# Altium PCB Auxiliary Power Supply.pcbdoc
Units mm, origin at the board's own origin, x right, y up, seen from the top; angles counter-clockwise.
Board outline 48 x 29.97 mm, 2 copper layers (Top Layer, Bottom Layer), stack 1.575 mm thick; 26 components, 15 nets, 76 pads, 29 vias.
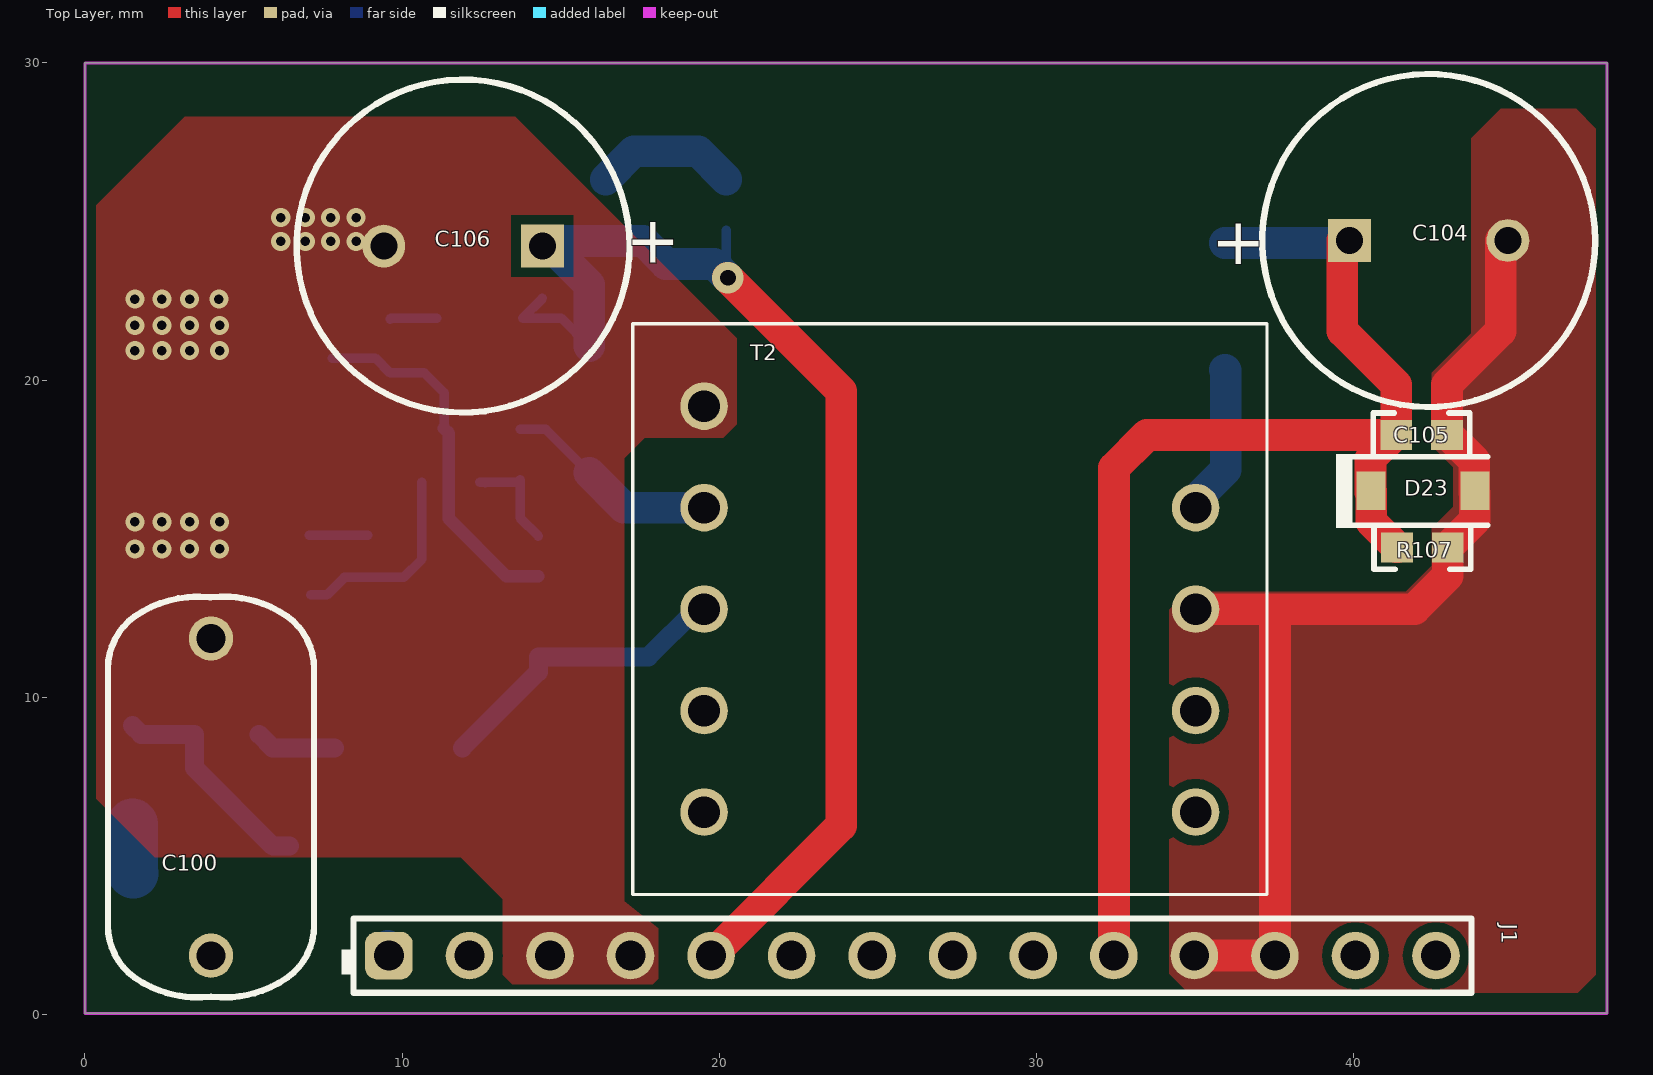
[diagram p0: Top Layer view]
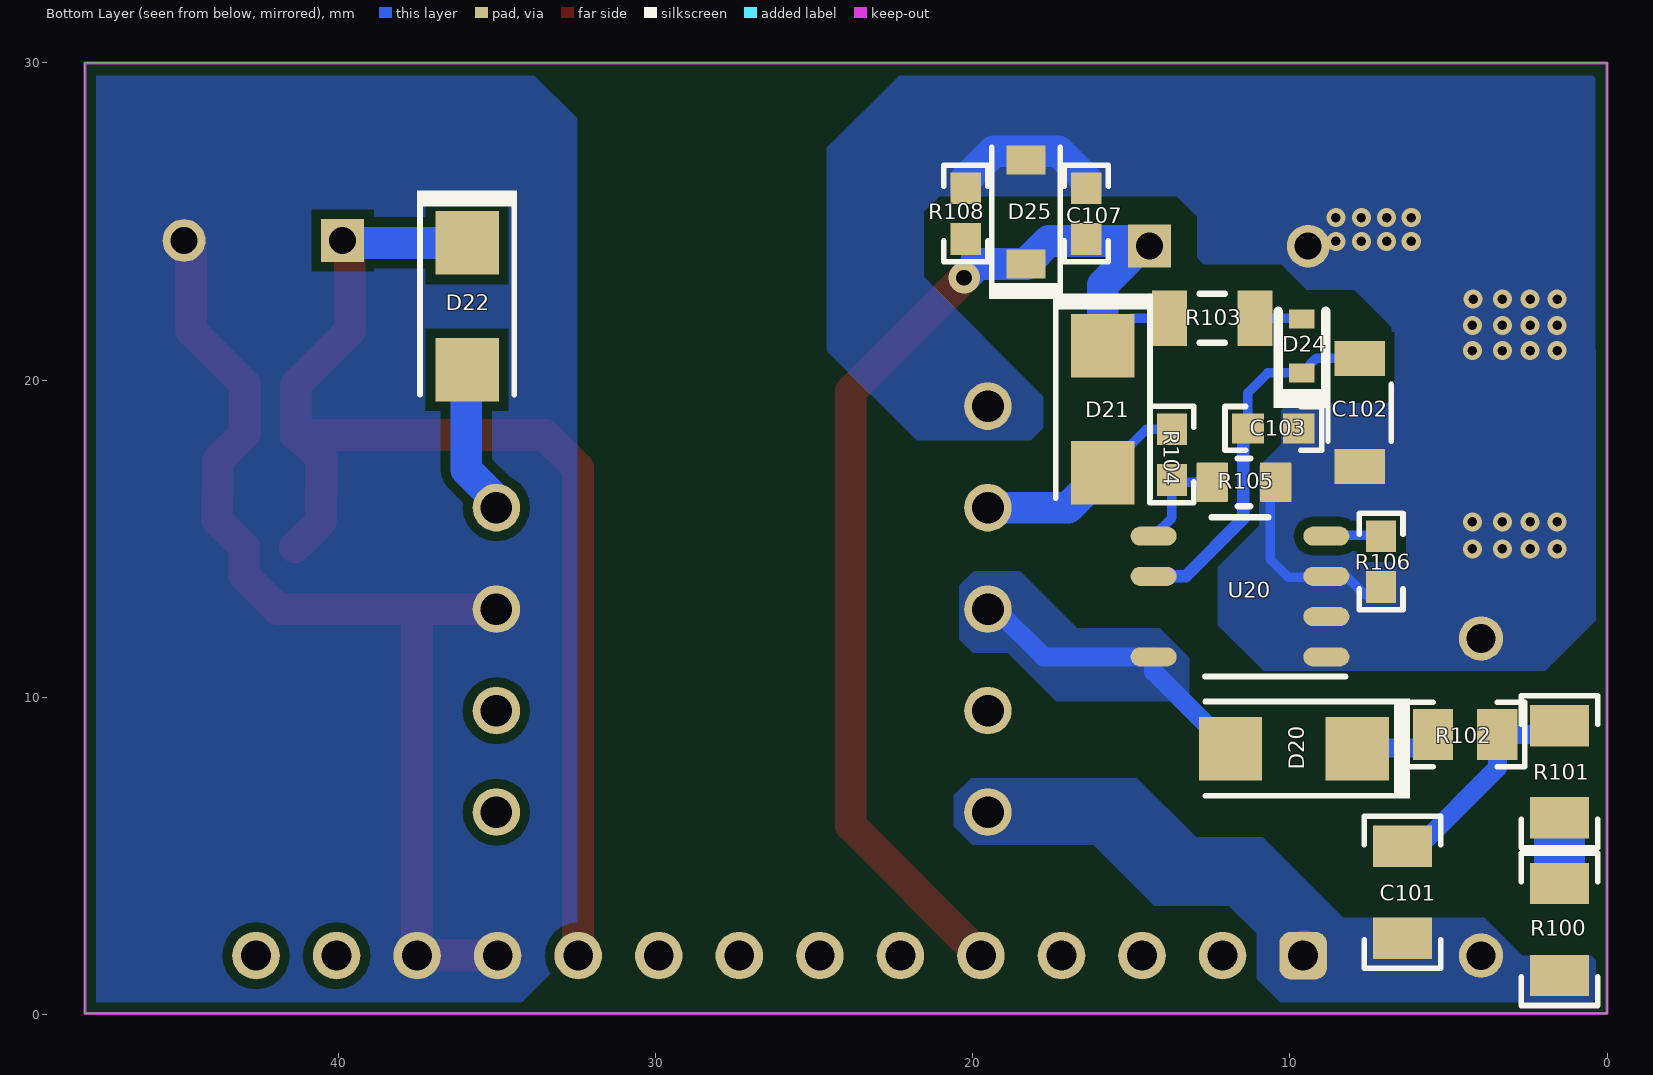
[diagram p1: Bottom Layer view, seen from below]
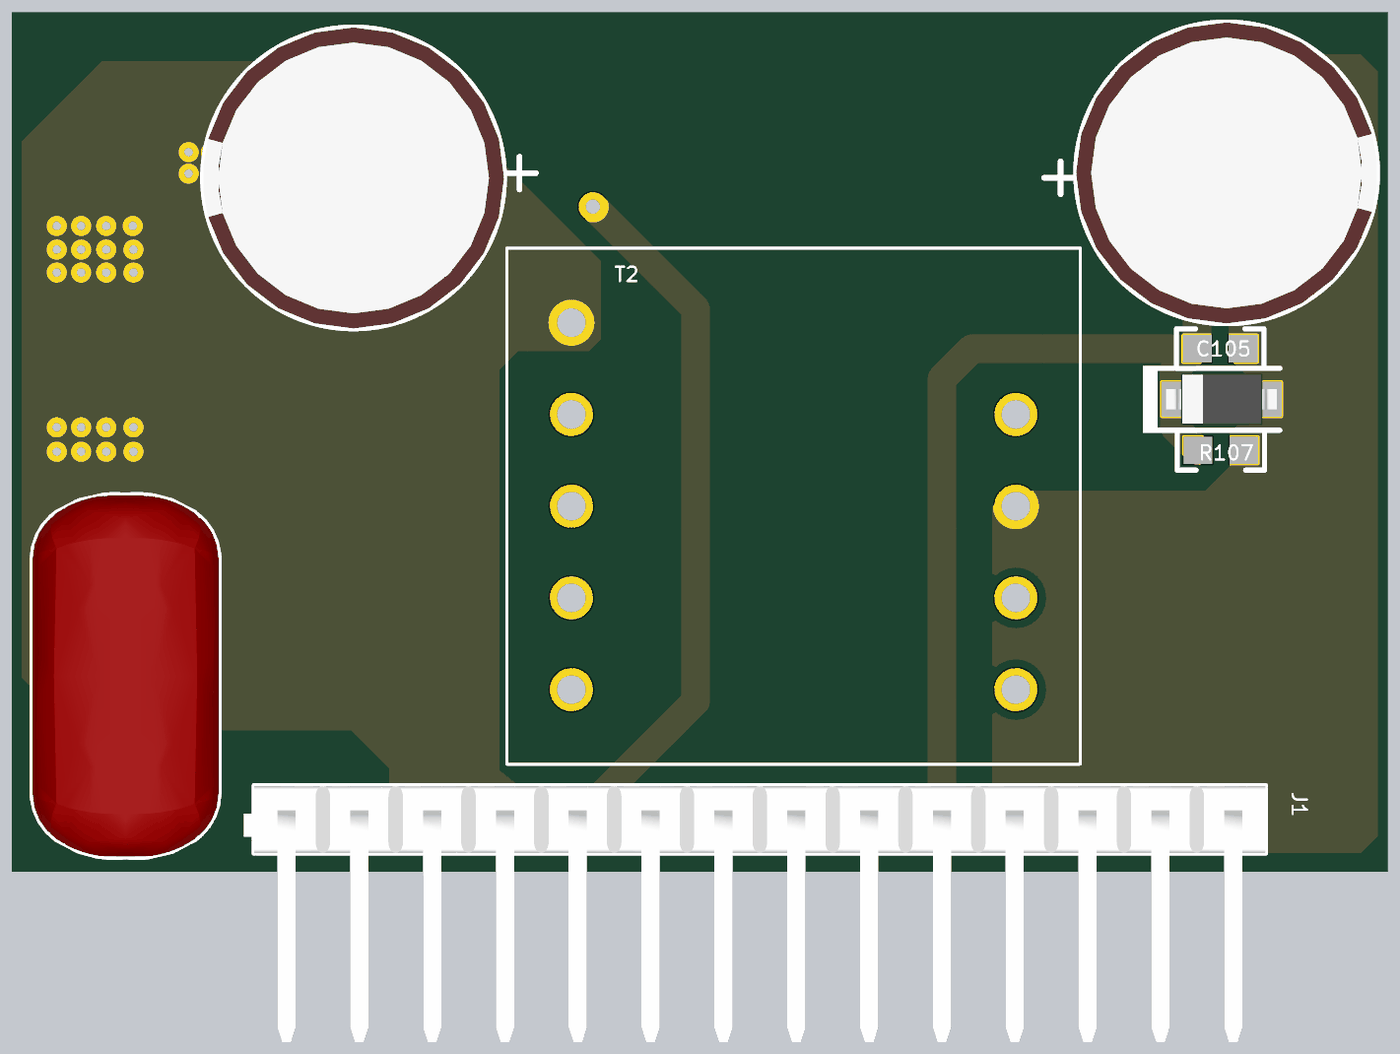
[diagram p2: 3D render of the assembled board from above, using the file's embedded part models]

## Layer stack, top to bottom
Top Solder: solder mask 0.0102, Solder Resist, Dk 3.5
Top Layer: signal copper 0.0356
Dielectric1: core 1.5037, FR-4, Dk 4.8
Bottom Layer: signal copper 0.0356
Bottom Solder: solder mask 0.0102, Solder Resist, Dk 3.5

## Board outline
0,0.025 48,0.025 48,30 0,30

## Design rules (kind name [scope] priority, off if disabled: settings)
AcuteAngle [All] p1: minimum=4.50000000000000E+0001 checktracksonly=FALSE
AssemblyTestPointUsage [All] p1: valid=2
BoardOutlineClearance BoardOutlineClearance_MountingHoles [OnCopper and InComponentClass('Mounting Holes')] p1: gap=0.4 ignorepadtopadclearanceinfootprint=FALSE
BoardOutlineClearance BoardOutlineClearance_Poly [OnCopper and IsPoly] p2: gap=0.3 ignorepadtopadclearanceinfootprint=FALSE
BoardOutlineClearance [OnCopper and Not InComponentClass('Logo') and not InComponentClass('FiducialMark') and not InRegion(1000,500,4000,800) and not InPoly] p3: gap=0.3 ignorepadtopadclearanceinfootprint=FALSE
Clearance Clearance_Keepouts [((IsTrack Or IsArc) And Not InPoly) And IsFree and IsKeepOut vs ((IsTrack Or IsArc) And Not InPoly) And IsFree and IsKeepOut] p1: gap=0 ignorepadtopadclearanceinfootprint=FALSE
Clearance Clearance_Poly [InPolygon] p2: gap=0.3 ignorepadtopadclearanceinfootprint=FALSE except(0: Arc-Hole Track-Hole SMDPad-Hole THPad-Hole Via-Hole Fill-Hole Poly-Hole Region-Hole Text-Hole)
Clearance Clearance_FiducialMark [IsKeepOut and InComponentClass('FiducialMark') vs IsPad and InComponentClass('FiducialMark')] p3: gap=0 ignorepadtopadclearanceinfootprint=FALSE
Clearance [All] p4: gap=0.2 ignorepadtopadclearanceinfootprint=FALSE except(0: Arc-Hole Track-Hole SMDPad-Hole THPad-Hole Via-Hole Fill-Hole Poly-Hole Region-Hole Text-Hole)
ComponentClearance ComponentClearance_MountingHoles_FiducialMarks [InComponentClass('Mounting Holes') vs InComponentClass('FiducialMark')] p1: gap=1.27 collisioncheckmode=3 verticalgap=0.254 showdistances=FALSE
ComponentClearance ComponentClearance_Shunt [InComponentClass('Header') vs InComponentClass('Shunt')] p2: gap=0 collisioncheckmode=3 verticalgap=0 showdistances=FALSE
ComponentClearance ComponentClearance_Logo [InComponentClass('Logo')] p3: gap=1.27 collisioncheckmode=3 verticalgap=0.254 showdistances=FALSE
ComponentClearance ComponentClearance_ScrewToNut [(HasFootprint('NY PMS 440 0025 PH')) vs (HasFootprint('Keystone_1902C'))] p4: gap=0.127 collisioncheckmode=3 verticalgap=0.254 showdistances=FALSE
ComponentClearance ComponentClearance_MountingHoles [InComponentClass('Mounting Holes')] p5: gap=6.35 collisioncheckmode=3 verticalgap=2540 showdistances=FALSE
ComponentClearance ComponentClearance_SmallPassives [HasFootprint('0201*') or HasFootprint('0402*') or HasFootprint('0508') or HasFootprint('0603*') or HasFootprint('0612') or HasFootprint('0805*') or HasFootprint('0815*') or HasFootprint('0830*') or HasFootprint('1206*') or HasFootprint('1210*') or HasFootprint('1808*') or HasFootprint('1812*') or HasFootprint('1825*') or HasFootprint('2010*') or HasFootprint('2220*') or HasFootprint('2225*') or HasFootprint('2512*') or HasFootprint('2728*') or HasFootprint('3518*') vs HasFootprint('0201*') or HasFootprint('0402*') or HasFootprint('0508') or HasFootprint('0603*') or HasFootprint('0612') or HasFootprint('0805*') or HasFootprint('0815*') or HasFootprint('0830*') or HasFootprint('1206*') or HasFootprint('1210*') or HasFootprint('1808*') or HasFootprint('1812*') or HasFootprint('1825*') or HasFootprint('2010*') or HasFootprint('2220*') or HasFootprint('2225*') or HasFootprint('2512*') or HasFootprint('2728*') or HasFootprint('3518*')] p6: gap=0.38 collisioncheckmode=3 verticalgap=0.254 showdistances=FALSE
ComponentClearance ComponentClearance_THtoSMT [IsThruComponent vs IsSMTComponent] p7: gap=0 collisioncheckmode=3 verticalgap=0 showdistances=FALSE
ComponentClearance ComponentClearance_THtoTH [IsThruComponent vs IsThruComponent] p8: gap=0 collisioncheckmode=3 verticalgap=0 showdistances=FALSE
ComponentClearance [All] p9: gap=0 collisioncheckmode=3 verticalgap=0 showdistances=FALSE
DiffPairsRouting [All] p1: maxlimit=2.54 minlimit=0.254 mostfreqgap=0.254 toplayer_minwidth=0.381 toplayer_maxwidth=0.381 toplayer_prefwidth=0.381 bottomlayer_minwidth=0.381 bottomlayer_maxwidth=0.381 bottomlayer_prefwidth=0.381 maxuncoupledlength=25.4
FabricationTestPointUsage TestPointUsage [All] p1: valid=2 allowmultiple=FALSE
FabricationTestpoint Testpoint [All] p1: side=3 testpointundercomponent=TRUE minsize=1.016 maxsize=2.54 preferedsize=1.524 minholesize=0 maxholesize=1.016 preferedholesize=0.813 testpointgrid=0.025 allowsidetop=TRUE allowsidebottom=TRUE usegrid=TRUE gridtolerance=0
FanoutControl Fanout_LCC [IsLCC] p1: bgadir=Out bgaviamode=Centered fanoutstyle=Auto fanoutdirection=Alternating viagrid=0.025 // Fanout_LCC (Default Rule)
FanoutControl Fanout_BGA [IsBGA] p2: bgadir=Out bgaviamode=Centered fanoutstyle=Auto fanoutdirection=Alternating viagrid=0.025 // Fanout_BGA (Default Rule)
FanoutControl Fanout_Default [All] p4: bgadir=Out bgaviamode=Centered fanoutstyle=Auto fanoutdirection=Alternating viagrid=0.025 // Fanout_Default (Default Rule)
FanoutControl Fanout_Small [(CompPinCount < 5)] p5: bgadir=Out bgaviamode=Centered fanoutstyle=Auto fanoutdirection=OutThenIn viagrid=0.025 // Fanout_Small (Default Rule)
HoleSize [All] p1: absolutevalues=TRUE maxlimit=6.375 minlimit=0.2 maxpercent=80.000 minpercent=20.000
MinimumAnnularRing MinimumAnnularRing_ThermalPadVias [IsVia and InAnyComponent] p1: minimumring=0.15
MinimumAnnularRing [All] p2: minimumring=0.203
MinimumSolderMaskSliver MinimumSolderMaskSliver_Logo [InComponentClass('Logo') vs InComponentClass('Logo')] p1: minsoldermaskwidth=0.018
MinimumSolderMaskSliver [All] p2: minsoldermaskwidth=0.1
PlaneConnect [All] p1: planeconnectstyle=Relief reliefexpansion=0.254 reliefentries=4 reliefconductorwidth=0.254 reliefairgap=0.254
PolygonConnect [All] p1: connectstyle=Direct reliefconductorwidth=0.254 reliefentries=4 polygonreliefangle="90 Angle" airgapwidth=0.254
RoutingVias ThermalPadVias [IsVia and InAnyComponent] p1: holewidth=0.2 width=0.5 viastyle="Through Hole" minholewidth=0.2 minwidth=0.5 maxholewidth=0.33 maxwidth=0.6
RoutingVias [All] p2: holewidth=0.406 width=0.864 viastyle="Through Hole" minholewidth=0.2 minwidth=0.66 maxholewidth=1.016 maxwidth=1.651
SilkToBoardRegionClearance [Not ((IsComment or IsDesignator) And (Hide <> 'False')) and not InRegion(1000,500,4000,800)] p1:
SilkToSilkClearance SilkToSilkClearance_Pb-FreeLogo [(HasFootprint('Pb-Free_Overlay_Medium') OR HasFootprint('Pb-Free_Overlay_Small')) vs (HasFootprint('Pb-Free_Overlay_Medium') OR HasFootprint('Pb-Free_Overlay_Small'))] p1: silktosilkclearance=0
SilkToSilkClearance [All] p2: silktosilkclearance=0.102
SilkToSolderMaskClearance SilkToComponentPadClearance [(IsPad or IsFill or IsRegion) and InAnycomponent] p1: minsilkscreentomaskgap=0.127 clearancetoexposedcopper=TRUE
SilkToSolderMaskClearance "Silk to Solder Mask Opening" [All] p2: minsilkscreentomaskgap=0.102 clearancetoexposedcopper=FALSE
SolderMaskExpansion [All] p1: expansion=0.05
Width [All] p1: maxlimit=2.54 minlimit=0.152 preferedwidth=0.254 checkconnectedcopper=TRUE
15 further rules are at their usual default settings.

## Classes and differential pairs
component class Header: J1

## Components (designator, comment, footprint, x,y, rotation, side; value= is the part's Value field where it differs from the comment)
C100 "ECW-FD2W474Q1" ECWFD_1260x650x1270 3.975,6.85 r90 top value=0.47uF
C101 "GRM31BR72J222KW01L" 1206 6.45,3.85 r90 bottom value=2200pF
C102 "C3216X5R1E476M160AC" 1206_190 7.8,18.975 r270 bottom value=47uF
C103 "GRM188R71E104KA01D" 0603 10.525,18.475 r180 bottom value=0.1uF
C104 "ELXZ250ELL471MJ16S" Chemi-Con_1000x1600 42.375,24.4 r0 top value=470uF
C105 "C0603C104K3RACTU" 0603 42.151,18.268 r0 top value=0.1uF
C106 "ELXZ250ELL471MJ16S" Chemi-Con_1000x1600 11.925,24.225 r180 top value=470uF
C107 "C0603C104K3RACTU" 0603 16.425,25.25 r90 bottom value=0.1uF
D20 "US1M-13-F" SMA 9.875,8.375 r0 bottom value=1000V
D21 "ES2DA-13-F" SMA 15.9,19.075 r270 bottom value=200V
D22 "ES2DA-13-F" SMA 35.95,22.325 r270 bottom value=200V
D23 "MMSZ4705T1G" SOD-123 42.2,16.505 r0 top value=18V
D24 "CDBU0245" SOD-523F 9.625,21.075 r90 bottom value=50V
D25 "MMSZ4705T1G" SOD-123 18.325,25.3 r90 bottom value=18V
J1 "TSW-114-08-L-S-RA" TE_4-644694-4 26.095,-0.182 r0 top
R100 "CRCW120620K0JNEA" 1206 1.5,2.675 r270 bottom value=20k
R101 "CRCW120620K0JNEA" 1206 1.5,7.65 r90 bottom value=20k
R102 "CRCW08050000Z0EA" 0805_HV 4.475,8.825 r180 bottom value=0
R103 "CRCW120620R0FKEA" 1206L 12.45,21.95 r180 bottom value=20.0
R104 "CRCW060351K0JNEA" 0603 13.725,17.65 r90 bottom value=51k
R105 "CRCW080518K2FKEA" 0805_HV1 11.45,16.775 r0 bottom value=18.2k
R106 "CRCW06031K50JNEA" 0603 7.125,14.275 r90 bottom value=1.5k
R107 "CRCW060318K0JNEA" 0603 42.175,14.725 r180 top value=18k
R108 "CRCW060318K0JNEA" 0603 20.225,25.25 r270 bottom value=18k
T2 "750344399" FLY_T1 27.275,12.775 r0 top
U20 "UCC28911DR" D0007A_N 11.575,13.175 r0 bottom

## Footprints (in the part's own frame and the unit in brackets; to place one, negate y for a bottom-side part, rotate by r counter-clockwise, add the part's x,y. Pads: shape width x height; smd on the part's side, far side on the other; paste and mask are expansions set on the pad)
0603 [mm] "0603 from SM-752 data"
  rect 1x0.95 smd: 1(-0.8,0) 2(0.8,0)
  silkscreen extent -1.52,-0.69 1.52,0.69, body extent -0.87,-0.47 0.87,0.47, height 1
0805_HV [mil] "0805 with 30mil clearance between pads"
  rect 50x63 smd: 1(-40,0) 2(40,0)
  silkscreen extent -74,-40 74,40, body extent -43,-29 43,29, height 57
0805_HV1 [mm] "Custom footprint based on analyzing multiple manufacturer recommendations"
  rrect10% 1x1.25 smd: 1(-1,0) 2(1,0)
  silkscreen extent -0.2,-0.75 0.2,0.75, body extent -1.1,-0.72 1.1,0.73, height 1.45
1206 [mm] "1206 from SM-752 data"
  rect 1.3x1.85 smd: 1(-1.45,0) 2(1.45,0)
  silkscreen extent -2.4,-1.21 2.4,1.21, body extent -1.7,-0.9 1.7,0.9, height 1.35
1206_190 [mm] "1206_190"
  rect 1.1x1.6 smd: 1(-1.7,0) 2(1.7,0)
  silkscreen extent -0.9,-1 0.9,1, body extent -1.75,-0.95 1.75,0.95, height 1.9
1206L [mm] "1206 from SM-752 data"
  rect 1.1x1.75 smd: 1(-1.35,0) 2(1.35,0)
  silkscreen extent -0.4,-0.77 0.4,0.77, body extent -1.7,-0.9 1.7,0.9, height 1.35
Chemi-Con_1000x1600 [mm] "TH, 2-Leads, Dia 10mm, Pin Spacing 5mm"
  rect 1.35x1.35 hole 0.85: 1(-2.5,0)
  round 1.35 hole 0.85: 2(2.5,0)
  silkscreen extent -5.25,-5.25 5.25,5.25, body extent -5.25,-5.25 5.26,5.25, height 17.5
D0007A_N [mm] "SOIC, 7-Leads, Body 4.9x3.9mm, Pitch 1.27mm, IPC Medium Density"
  oval 1.45x0.6 smd: 1(-2.725,1.905) 2(-2.725,0.635) 3(-2.725,-0.635) 4(-2.725,-1.905) 5(2.725,-1.905) 6(2.725,-0.635) 8(2.725,1.905)
  silkscreen extent -3.32,-2.5 1.1,2.52, body extent -3.01,-2.45 3.01,2.45, height 1.75
ECWFD_1260x650x1270 [mm] "TH, 2-Leads, Body 12.6x6.5mm"
  round 1.4 hole 0.9: 1(-5,0) 2(5,0)
  silkscreen extent -6.32,-3.25 6.32,3.25, body extent -6.31,-3.25 6.31,3.25, height 12.71
FLY_T1 [mm]
  round 1.5 hole 1: 1(7.75,3.2) 2(7.75,0) 3(-7.75,0) 4(-7.75,-6.4) 5(-7.75,3.2) 6(-7.75,6.4) ""(-7.75,-3.2) ""(7.75,-6.4) ""(7.75,-3.2)
  silkscreen extent -10,-9 10,9
SMA [mm] "Molded Diode, 2-Leads, Body 4.3x2.6mm, IPC Medium Density, based on OnSemi component dimensions and land pattern"
  rect 2x2 smd: 1(-2,0) 2(2,0)
  silkscreen extent -3.66,-1.57 2.79,1.57, body extent -2.6,-1.3 2.6,1.3, height 2.42
SOD-123 [mm] "On Semi recommended land pattern"
  rect 0.915x1.22 smd: 1(-1.637,0) 2(1.637,0)
  silkscreen extent -2.74,-1.17 2.03,1.17, body extent -1.93,-0.9 1.93,0.9, height 1.35
SOD-523F [mm] "COMCHIP"
  rect 0.6x0.8 smd paste-0.05: 1(-0.85,0) 2(0.85,0)
  silkscreen extent -1.95,-0.9 1.1,0.9, body extent -0.9,-0.5 0.9,0.5, height 0.85
TE_4-644694-4 [mm] "Header, 100 mil, 14x1, R/A, TH"
  rrect50% 1.5x1.5 hole 0.94: 1(-16.51,2.032)
  round 1.5 hole 0.94: 2(-13.97,2.032) 3(-11.43,2.032) 4(-8.89,2.032) 5(-6.35,2.032) 6(-3.81,2.032) 7(-1.27,2.032) 8(1.27,2.032) 9(3.81,2.032) 10(6.35,2.032) 11(8.89,2.032) 12(11.43,2.032) 13(13.97,2.032) 14(16.51,2.032)
  silkscreen extent -18,0.86 17.63,3.2, body extent -17.63,-5.74 17.63,3.2, height 6.67

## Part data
C100: "CAP, Film, 0.47 µF, 450 V, +/- 10%, TH", Cap_Case=12.6x6.5x12.7mm, Manufacturer=Panasonic, Supplier Part Number 1=P16727-ND, Tolerance_%=10, Value1=Unknown, Value2=450V, ValueDisplayed=0.47µF
C101: "CAP, CERM, 2200 pF, 630 V,+/- 10%, X7R, 1206", Cap_Case=1206, Manufacturer=MuRata, Supplier Part Number 1=490-3508-1-ND, TempCo=X7R, Tolerance_%=10, Value2=630V, ValueDisplayed=2200pF
C102: "CAP, CERM, 47 µF, 25 V,+/- 20%, X5R, 1206", Cap_Case=1206, Manufacturer=TDK, Supplier Part Number 1=445-8047-1-ND, TempCo=X5R, Tolerance_%=20, Value2=25V, ValueDisplayed=47µF
C103: library part CMP-0007404-4, "CAP, CERM, 0.1 uF, 25 V, +/- 10%, X7R, 0603", Cap_Case=0603, Manufacturer=MuRata, Supplier Part Number 1=490-1524-1-ND, TempCo=X7R, Tolerance_%=10%, Value1=Unknown, Value2=25V, ValueDisplayed=0.1uF
C104: library part CMP-0010480-1, "CAP, AL, 470 uF, 25 V, +/- 20%, AEC-Q200 Grade 2, TH", Cap_Case=10x16mm, Manufacturer=Chemi-Con, Supplier Part Number 1=565-1958-ND, Tolerance_%=20%, Value1=Unknown, Value2=25V, ValueDisplayed=470uF
C105 C107: "CAP, CERM, 0.1 µF, 25 V,+/- 10%, X7R, 0603", Cap_Case=0603, Manufacturer=Kemet, Supplier Part Number 1=399-1281-1-ND, TempCo=X7R, Tolerance_%=10, Value2=25V, ValueDisplayed=0.1µF
C106: "CAP, AL, 470 µF, 25 V, +/- 20%, AEC-Q200 Grade 2, TH", Cap_Case=10x16mm, Manufacturer=Chemi-Con, Supplier Part Number 1=565-1958-ND, Tolerance_%=20, Value2=25V, ValueDisplayed=470µF
D20: "Diode, Ultrafast, 1000 V, 1 A, SMA", Manufacturer="Diodes Inc.", Supplier Part Number 1=US1M-FDICT-ND, Value1=1A, Value2=1.7V
D21 D22: "Diode, Superfast Rectifier, 200 V, 2 A, SMA", Manufacturer="Diodes Inc.", Supplier Part Number 1=ES2DA-FDICT-ND, Value1=2A, Value2=0.92V
D23 D25: "Diode, Zener, 18 V, 500 mW, SOD-123", Manufacturer="ON Semiconductor", Power_W=0.5, Supplier Part Number 1=MMSZ4705T1GOSCT-ND, Value1=0.5W
D24: "Diode, Schottky, 50 V, 0.2 A, SOD-523F", Manufacturer="Comchip Technology", Supplier Part Number 1=641-1284-1-ND, Value1=0.2A, Value2=0.55V
J1: library part 4-644694-4, "Header, 100 mil, 14x1, Gold, R/A, TH", Color=Natural, Manufacturer=Samtec, Supplier Part Number 1=SAM1043-14-ND
R100 R101: "RES, 20 k, 5%, 0.25 W, 1206", Manufacturer=Vishay-Dale, Power_W=0.25, Supplier Part Number 1=541-20KECT-ND, TempCo="200 ppm/C", Tolerance_%=5, Value1=5%, Value2=0.25W, Value_Code=20k0, ValueDisplayed=20k
R102: "RES, 0, 5%, 0.125 W, 0805", Manufacturer=Vishay-Dale, Power_W=0.125, Supplier Part Number 1=541-0.0ACT-ND, TempCo="200 ppm/C", Tolerance_%=5, Value1=5%, Value2=0.125W, Value_Code=0000, ValueDisplayed=0
R103: "RES, 20.0, 1%, 0.25 W, 1206", Manufacturer=Vishay-Dale, Power_W=0.25, Supplier Part Number 1=541-20.0FCT-ND, TempCo="100 ppm/C", Tolerance_%=1, Value1=1%, Value2=0.25W, Value_Code=20R0, ValueDisplayed=20.0
R104: "RES, 51 k, 5%, 0.1 W, 0603", Manufacturer=Vishay-Dale, Power_W=0.1, Supplier Part Number 1=541-51KGCT-ND, TempCo="200 ppm/C", Tolerance_%=5, Value1=5%, Value2=0.1W, Value_Code=51k0, ValueDisplayed=51k
R105: "RES, 18.2 k, 1%, 0.125 W, 0805", Manufacturer=Vishay-Dale, Power_W=0.125, Supplier Part Number 1=541-18.2KCCT-ND, TempCo="100 ppm/C", Tolerance_%=1, Value1=1%, Value2=0.125W, Value_Code=18k2, ValueDisplayed=18.2k
R106: "RES, 1.5 k, 5%, 0.1 W, 0603", Manufacturer=Vishay-Dale, Power_W=0.1, Supplier Part Number 1=541-1.5KGCT-ND, TempCo="200 ppm/C", Tolerance_%=5, Value1=5%, Value2=0.1W, Value_Code=1k50, ValueDisplayed=1.5k
R107 R108: library part CMP-0025727-4, "RES, 18 k, 5%, 0.1 W, AEC-Q200 Grade 0, 0603", Manufacturer=Vishay-Dale, Power_W=100mW, Supplier Part Number 1=541-18KGCT-ND, TempCo="200 ppm/C", Tolerance_%=5%, Value2=0.1W, Value_Code=18k0, ValueDisplayed=18k
T2: library part "Trans3 Ideal", "750344399 Wuth", Manufacturer=Wurth
U20: library part CMP-0074093-2, "700V Flyback Switcher with Constant-Voltage Constant-Current and Primary-side Regulation, D0007A (SOIC-7)", Alternate Manufacturer="Texas Instruments", Alternate PartNumber=UCC28911D

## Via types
v1: diameter 0.6, hole 0.3, Top Layer to Bottom Layer, 28 vias
v2: diameter 1, hole 0.5, Top Layer to Bottom Layer, 1 vias

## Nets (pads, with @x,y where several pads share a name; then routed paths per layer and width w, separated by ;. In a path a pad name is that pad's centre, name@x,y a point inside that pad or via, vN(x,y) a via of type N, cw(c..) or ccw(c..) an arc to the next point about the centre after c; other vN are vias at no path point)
390V: C100.1 C101.1 J1.1 R100.2 T2.4 | length 0.1
  Bottom Layer w1: J1.1@9.547,2.15 J1.1@9.59,2.107
NetC101_2: C101.2 R101.2 R102.2 | length 7.1
  Bottom Layer w0.6: R101.2 1.775,8.825 R102.2 3.459,7.766 5.925,5.3 C101.2
NetD20_1: D20.1 R102.1 | length 2.6
  Bottom Layer w0.6: R102.1 5.916,8.4 D20.1@7.875,8.4
NetD20_2: D20.2 T2.3 U20.8 | length 9.5
  Bottom Layer w0.6: D20.2@11.9,8.4 14.3,10.8 U20.8 17.77,11.27 T2.3@19.275,12.775
NetD21_2: D21.2 R104.2 T2.5 | length 6.6
  Bottom Layer w0.3: R104.2 14.525,18.45 D21.2
  Bottom Layer w1: D21.2 17,15.975 T2.5@19.275,15.975
NetD22_2: D22.2 T2.1 | length 4.9
  Bottom Layer w1: T2.1@34.775,15.975 35.975,17.175 35.975,20.3 D22.2
NetD24_2: D24.2 R103.2 | length 1.5
  Bottom Layer w0.3: D24.2 9.65,21.95 R103.2
NetR100_1: R100.1 R101.1 | length 1.8
  Bottom Layer w0.3: R100.1@1.525,4.175 R100.1@1.525,4.45
  Bottom Layer w1.6: R101.1@1.5,6 1.5,4.475 R100.1@1.525,4.45
NetR104_1: R104.1 R105.2 U20.5 | length 3.3
  Bottom Layer w0.3: R105.2 R105.2@12.625,16.775 ; R105.2@12.625,16.755 R105.2@12.625,16.775 ; U20.5 13.725,15.655 R104.1 13.65,16.775 R105.2@12.625,16.775
NetR106_2: R106.2 U20.4 | length 1.8
  Bottom Layer w0.3: R106.2@7.075,15.1 U20.4@8.911,15.1
PGND: C100.2 C102.2 C103.2 C106.2 C107.2 D25.2 J1.3 J1.4 R105.1 R106.1 R108.1 T2.6 U20.1 U20.2 U20.3 | length 10.9
  Bottom Layer w0.3: R106.1@7.125,13.225 7.631,13.225 8.181,13.775 10.05,13.775 10.625,14.35 R105.1@10.625,16.775
  Bottom Layer w1: C107.2@16.425,26.325 17.313,27.213 19.338,27.213 R108.1@20.225,26.325
  other v1: 1.575,14.675 2.425,14.675 3.3,14.675 4.25,14.675 1.575,15.525 2.425,15.525 3.3,15.525 4.25,15.525 1.575,20.925 2.425,20.925 3.3,20.925 4.25,20.925 1.575,21.725 2.425,21.725 3.3,21.725 4.25,21.725 1.575,22.55 2.425,22.55 3.3,22.55 4.225,22.55 6.175,24.375 6.95,24.375 7.75,24.375 8.55,24.375 6.175,25.125 6.95,25.125 7.75,25.125 8.55,25.125
Pri_15V: C106.1 C107.1 D21.1 D25.1 J1.5 R103.1 R108.2 | length 41.7
  Top Layer w1: J1.5 23.85,5.955 23.85,19.65 v2(20.275,23.225)
  Bottom Layer w0.3: C106.1@14.336,24.386 14.675,24.725 C107.1@16.325,24.725 ; 14.425,22.575 R103.1 15.025,21.95 D21.1 ; R108.2@20.225,24.725 R108.2 20.225,23.275 v2(20.275,23.225)
  Bottom Layer w1: C106.1@14.336,24.386 C106.1@14.514,24.386 ; D21.1 15.9,23 C106.1@14.514,24.386 ; D25.1@18.261,23.726 17.601,24.386 C106.1@14.514,24.386 ; D25.1 19.837,23.663 v2@20.225,23.275
Sec_15V: C104.1 C105.1 D22.1 D23.1 J1.10 R107.2 | length 39.2
  Top Layer w1: J1.10@32.45,2.107 32.45,17.225 33.493,18.268 C105.1@41.293,18.268 ; C104.1@39.65,24.4 39.65,21.55 41.35,19.85 41.35,18.325 C105.1@41.293,18.268 ; D23.1@40.538,16.45 40.538,17.512 C105.1@41.293,18.268 ; D23.1@40.562,16.5 40.562,15.538 R107.2 ; C105.1 C105.1@41.293,18.268
  Bottom Layer w1: D22.1 C104.1@39.625,24.325
SGND: C104.2 C105.2 D23.2 J1.11 J1.12 R107.1 T2.2 | length 33.9
  Top Layer w1: T2.2@34.775,12.775 T2.2 37.625,12.775 ; J1.11 J1.12 ; J1.12@37.53,2.107 37.53,12.68 37.625,12.775 ; C104.2@44.65,24.4 44.65,21.55 42.95,19.85 42.95,18.325 43.813,17.462 43.813,16.45 43.825,16.438 43.825,15.575 R107.1 42.975,13.825 41.925,12.775 37.625,12.775
VDD: C102.1 C103.1 D24.1 U20.6 | length 11.6
  Bottom Layer w0.3: C102.1@7.8,20.691 9.159,20.691 D24.1 10.7,20.225 11.325,19.6 C103.1
  Bottom Layer w0.4: C103.1 11.475,18.325 11.475,15.625 13.29,13.81 U20.6
pads on no net: J1.2 J1.6 J1.7 J1.8 J1.9 J1.13 J1.14 T2.
copper on no net: | length 0.6
  Top Layer w0.3: 42.61,2.107 42.932,2.107 42.757,1.932

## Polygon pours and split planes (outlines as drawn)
390V on Bottom Layer "Bottom Layer-No Net 3" (solid, pour order 8): 0.5,1.85 2.675,1.85 3.875,3.05 6.825,3.05 8.325,3.05 10.85,5.575 12.95,5.575 14.825,7.45 20.05,7.45 20.6,6.9 20.6,5.925 20.025,5.35 16.2,5.35 14.275,3.425 11.925,3.425 11.05,2.55 11.05,1.125 10.175,0.25 6.875,0.25 0.6,0.25 0.29,0.56 0.29,1.64
SGND on Bottom Layer "Bottom Layer-No Net 1" (solid, remove dead copper, pour order 36): 33.825,29.6 47.643,29.6 47.643,0.275 34.325,0.275 32.475,2.125 32.475,28.25
PGND on Bottom Layer "PGND" (solid, pour order 46): 0.357,12.418 1.95,10.825 10.825,10.825 12.275,12.275 12.275,14.104 10.975,15.404 10.975,17.275 10.275,17.975 10.275,19.05 10.05,19.275 6.95,19.275 6.784,19.441 6.784,21.659 7.975,22.85 9.475,22.85 10.625,24 10.625,29.35 10.375,29.6 0.45,29.6 0.375,29.525
PGND on Bottom Layer "PGND" (solid, pour order 48): 21.775,18.1 24.6,20.925 24.6,27.325 22.325,29.6 10.25,29.6 10.25,23.65 12.725,23.65 12.925,23.85 12.925,25.15 13.575,25.8 21.05,25.8 21.55,25.3 21.55,23.25 17.775,19.475 17.775,18.5 18.175,18.1
NetD20_2 on Bottom Layer "PGND" (solid, pour order 50): 20.425,11.825 20,11.4 18.9,11.4 17.375,9.875 13.175,9.875 13.175,11.25 14.1,12.175 16.7,12.175 18.5,13.975 19.975,13.975 20.425,13.525
PGND on Top Layer "Bottom Layer-No Net" (solid, pour order 2): 20.125,18.175 17.65,18.175 17.013,17.538 17.012,3.562 18.075,2.71 18.075,1.113 17.912,0.95 13.475,0.95 13.175,1.25 13.175,3.619 11.844,4.95 2.2,4.95 0.3,6.85 0.3,25.45 3.15,28.3 13.575,28.3 20.55,21.325 20.55,18.6
SGND on Top Layer "SGND" (solid, pour order 58): 43.725,21.475 42.475,20.225 42.475,17.925 43.15,17.25 43.15,16 42.475,15.325 42.475,14.15 41.65,13.325 34.775,13.325 34.2,12.75 34.2,1.275 34.793,0.682 47.081,0.682 47.65,1.251 47.65,27.925 47.025,28.55 44.65,28.55 43.725,27.625

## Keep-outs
Keep-Out Layer:
  the board outline again, w0.1
  text ".Layer_Name" at 14.656,-21.806 h1.52

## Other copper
Top Layer:
  text ".Layer_Name" at 14.656,-21.806 h1.52
Bottom Layer:
  text ".Layer_Name" at 14.656,-21.806 h1.52

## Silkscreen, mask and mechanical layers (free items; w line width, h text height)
Top Overlay:
  text ".Layer_Name" at 14.656,-21.806 h1.52
Bottom Overlay:
  text ".Layer_Name" at 14.656,-21.806 h1.52
Top Paste:
  text ".Layer_Name" at 14.656,-21.806 h1.52
Bottom Paste:
  text ".Layer_Name" at 14.656,-21.806 h1.52
Top Solder:
  text ".Layer_Name" at 14.656,-21.806 h1.52
  text ".Layer_Name" at 14.656,-21.806 h1.52
Bottom Solder:
  text ".Layer_Name" at 14.656,-21.806 h1.52
Drill Guide:
  text ".Layer_Name" at 14.656,-21.806 h1.52
M1 Board Outline:
  lines w0.254: 0,0 0,30 48,30 48,0 0,0
  text ".Layer_Name" at 14.656,-21.806 h1.52
M2 Board Dimensions:
  rectangle: 0,-6.985 3.175,-3.81
  rectangle: 3.175,-10.16 12.7,-6.985
  lines w0.178: 0,-6.985 25.4,-6.985 ; 3.175,-10.16 3.175,-3.81 ; 6.35,-10.16 6.35,-3.81 ; 12.7,-10.16 12.7,-3.81 ; 19.05,-10.16 19.05,-3.81 ; 0,-10.16 25.4,-10.16 25.4,-3.81 0,-3.81 0,-10.16
  text ".Layer_Name" at 14.656,-21.806 h1.52
M3 3D STEP Top:
  text ".Layer_Name" at 14.656,-21.806 h1.52
M4 3D STEP Bottom:
  text ".Layer_Name" at 14.656,-21.806 h1.52
M5 Assembly Top:
  lines w0.254: -7.417,-23.626 160.223,-23.626 ; -7.417,-18.462 160.274,-18.462 ; -7.417,-13.297 -7.417,-28.791 94.31,-28.791 160.274,-28.791 160.274,-13.297 -7.404,-13.297 -7.404,-28.791 32.614,-28.791 ; 55.194,-28.791 55.194,-13.297 ; 87.376,-18.462 87.376,-13.297 ; 108.712,-18.462 108.712,-13.297 ; 124.511,-28.956 124.511,-23.804
  text "COMPONENTS MARKED 'DNP' SHOULD NOT BE POPULATED." at 29.299,-8.09 h0.5
  text "ASSEMBLY VARIANT:" at 29.286,-11.024 h0.5
  text ".VariantName" at 55.601,-11.024 h0.5
  text "PCB VIEWED FROM TOP SIDE" at -5.804,-16.654 h1.52
  text "BOARD #:" at 57.099,-16.654 h1.52
  text ".PRJ_Number" at 70.955,-16.654 h1.52
  text "REV:" at 92.405,-16.654 h1.52
  text ".PCB_Rev" at 99.809,-16.654 h1.52
  text "SVN REV:" at 113.69,-16.654 h1.52
  text ".VersionControl_RevNumber" at 126.543,-16.654 h1.52
  text "TID #:" at 57.099,-21.819 h1.52
  text ".TID" at 70.955,-21.819 h1.52
  text "PLOT NAME =" at -5.804,-27.034 h1.52
  text ".plot_File_Name" at 14.656,-27.034 h1.52
  text "GENERATED    :" at 57.15,-27.034 h1.52
  text ".Print_Date" at 79.235,-27.034 h1.52
  text ".Print_Time" at 97.752,-27.034 h1.52
  text "TEXAS INSTRUMENTS" at 129.87,-27.034 h1.52
M6 Assembly Bottom:
  lines w0.254: -7.429,-18.474 160.261,-18.474 ; -7.379,-23.639 160.261,-23.639 ; 28.334,-28.969 28.334,-23.817 ; 44.133,-18.474 44.133,-13.31 ; 65.468,-18.474 65.468,-13.31 ; 97.65,-28.804 97.65,-13.31 ; 120.231,-28.804 160.249,-28.804 160.249,-13.31 -7.429,-13.31 -7.429,-28.804 58.534,-28.804 160.261,-28.804 160.261,-13.31
  text "COMPONENTS MARKED 'DNP' SHOULD NOT BE POPULATED." at 154.991,-8.077 h0.5
  text ".VariantName" at 128.473,-11.024 h0.5
  text "ASSEMBLY VARIANT:" at 154.864,-11.024 h0.5
  text ".VersionControl_RevNumber" at 26.302,-16.667 h1.52
  text "SVN REV:" at 39.154,-16.667 h1.52
  text ".PCB_Rev" at 53.035,-16.667 h1.52
  text "REV:" at 60.439,-16.667 h1.52
  text ".PRJ_Number" at 81.89,-16.667 h1.52
  text "BOARD #:" at 95.745,-16.667 h1.52
  text "PCB VIEWED FROM BOTTOM SIDE" at 158.648,-16.667 h1.52
  text ".TID" at 81.89,-21.831 h1.52
  text "TID #:" at 95.745,-21.831 h1.52
  text "TEXAS INSTRUMENTS" at 22.974,-27.047 h1.52
  text ".Print_Time" at 55.093,-27.047 h1.52
  text ".Print_Date" at 73.609,-27.047 h1.52
  text "GENERATED    :" at 95.694,-27.047 h1.52
  text ".plot_File_Name" at 138.189,-27.047 h1.52
  text "PLOT NAME =" at 158.648,-27.047 h1.52
M9 Title Sheet:
  drawing of 57 lines, arcs and shapes, not listed
  text "1" at 18.792,204.127 h1.78
  text "2" at 82.182,204.127 h1.78
  text "3" at 145.411,204.127 h1.78
  text "4" at 209.08,204.127 h1.78
  text "5" at 272.555,204.127 h1.78
  text "6" at 336.182,204.127 h1.78
  text "A" at -10.579,175.095 h1.78
  text "A" at 365.341,175.095 h1.78
  text "B" at -10.579,114.643 h1.78
  text "B" at 365.341,114.643 h1.78
  text "C" at -10.579,54.318 h1.78
  text "C" at 365.341,54.318 h1.78
  text "PROJECT TITLE:" at 288.125,7.048 h1.14
  text ".PRJ_Title" at 289.395,3.662 h1.78
  text "DESIGNED FOR:" at 288.125,-0.597 h1.14
  text ".PRJ_Customer" at 289.395,-4.153 h1.78
  text "D" at -10.579,-5.88 h1.78
  text "D" at 365.341,-5.88 h1.78
  text "FILE NAME:" at 288.125,-8.217 h1.14
  text ".PCB_File_Name_No_Path" at 289.395,-11.265 h1.78
  text "Texas Instruments (TI) and/or its licensors do not warrant the accuracy or completeness of this specification" at 161.9,-15.376 h1.14
  text "ENGINEER:" at 288.125,-15.583 h1.14
  text "LAYOUT BY:" at 326.352,-15.583 h1.14
  text "or any information contained therein. TI and/or its licensors do not warrant that this design will meet" at 160.757,-18.237 h1.14
  text ".PRJ_Engineer" at 289.395,-19.52 h1.78
  text ".PCB_Layout" at 327.635,-19.52 h1.78
  text "the specifications, will be suitable for your application or fit for any particular purpose, or will operate in" at 160.757,-21.099 h1.14
  text ".Layer_Name" at 14.656,-21.806 h1.52
  text "ALTIUM DESIGNER VERSION:" at 326.352,-23.457 h1.14
  text "an implementation. TI and/or its licensors do not warrant that the design is production worthy. You should" at 160.757,-23.961 h1.14
  text "completely validate and test your design implementation to confirm the system functionality for your application." at 161.9,-26.822 h1.14
  text ".print_Scale" at 289.395,-26.843 h1.78
  text ".Application_BuildNumber" at 327.635,-26.843 h1.78
  text "1" at 18.792,-32.093 h1.78
  text "2" at 82.182,-32.093 h1.78
  text "3" at 145.411,-32.093 h1.78
  text "4" at 209.08,-32.093 h1.78
  text "5" at 272.555,-32.093 h1.78
  text "6" at 336.182,-32.093 h1.78
M10 Fab Notes:
  drawing of 189 lines, arcs and shapes, not listed
  text "DESIGN INFORMATION" at 314.503,161.447 h1.52
  text "MIN. TRACK WIDTH:" at 298.131,158.091 h1.52
  text "8" at 325.976,158.091 h1.52
  text "MIL" at 329.907,158.091 h1.52
  text "MIN. CLEARANCE:" at 298.131,154.938 h1.52
  text "0.2" at 324.452,154.938 h1.52
  text "mm" at 329.907,154.938 h1.52
  text "MIN. VIA PAD SIZE:" at 298.131,151.785 h1.52
  text "24" at 325.214,151.785 h1.52
  text "MIL" at 329.907,151.785 h1.52
  text "0.05mm (2MIL)" at 315.784,148.486 h1.52
  text "MINIMUM ANNULAR RING" at 289.769,148.277 h1.52
  text "EXTERNAL" at 333.768,148.277 h1.52
  text "PER" at 294.849,145.48 h1.52
  text "IPC-D-275 CLASS 2 LEVEL C" at 300.437,145.48 h1.52
  text "MIL, HOLES" at 338.238,142.928 h1.52
  text "+/-" at 328.27,142.709 h1.52
  text "+/-" at 349.961,142.709 h1.52
  text "REGISTRATION TOLERANCES:" at 289.769,142.682 h1.52
  text "METAL" at 320.243,142.682 h1.52
  text "5" at 334.879,142.683 h1.52
  text "3" at 356.037,142.683 h1.52
  text "MIL" at 358.99,142.682 h1.52
  text "HOLE SIZE TOLERANCE (UNLESS OTHERWISE SPECIFIED):" at 289.769,140.185 h1.52
  text "+/-" at 349.961,140.112 h1.52
  text "3" at 356.037,140.085 h1.52
  text "MIL" at 358.99,140.085 h1.52
  text "MATERIAL:" at 287.87,136.589 h1.52
  text "FR-4 High Tg" at 312.926,133.324 h1.52
  text "X" at 309.257,133.122 h1.52
  text "FR-408" at 298.563,133.007 h1.52
  text "OTHER" at 336.358,133.007 h1.52
  text "62 MIL (1.6mm) +/-10%" at 306.694,129.374 h1.52
  text "X" at 303.643,129.312 h1.52
  text "THICKNESS:" at 289.769,129.165 h1.52
  text "OTHER" at 339.33,129.165 h1.52
  text "TOLERANCE:" at 289.769,125.652 h1.52
  text "X" at 311.314,125.652 h1.52
  text "ANSI IPC-6012 TYPE 3 CLASS 2" at 315.836,125.652 h1.52
  text "OTHER +/-" at 315.835,121.989 h1.52
  text "BOW & TWIST:" at 289.769,118.302 h1.52
  text "X" at 311.314,118.302 h1.52
  text "ANSI IPC-6012 TYPE 3 CLASS 2" at 315.836,118.302 h1.52
  text "OTHER +/-" at 315.835,114.576 h1.52
  text "DRILLING:" at 287.87,111.258 h1.52
  text "NC_DRILL FILES" at 332.599,108.586 h1.52
  text "REFERENCE:" at 289.769,108.486 h1.52
  text "X" at 306.463,108.484 h1.52
  text "AS SHOWN" at 310.984,108.486 h1.52
  text "X" at 329.348,108.486 h1.52
  text "OTHER" at 340.168,104.873 h1.52
  text "PTH COPPER THICKNESS:" at 289.761,104.783 h1.52
  text "X" at 318.697,104.783 h1.52
  text "20-30 um" at 321.948,104.783 h1.52
  text "BOARD FINISH:" at 287.87,101.034 h1.52
  text "SILKSCREEN:" at 291.812,98.237 h1.52
  text "X" at 316.14,98.237 h1.52
  text "TOP" at 319.112,98.237 h1.52
  text "X" at 329.094,98.237 h1.52
  text "BOTTOM" at 332.091,98.237 h1.52
  text "SILKSCREEN COLOR:" at 291.812,94.295 h1.52
  text "X" at 316.115,94.295 h1.52
  text "WHITE" at 319.112,94.295 h1.52
  text "OTHER" at 332.091,94.295 h1.52
  text "X" at 319.442,90.652 h1.52
  text "GREEN" at 322.439,90.652 h1.52
  text "OTHER" at 338.136,90.652 h1.52
  text "SOLDER RESIST COLOR:" at 291.812,90.477 h1.52
  text "X" at 319.442,86.734 h1.52
  text "MATTE" at 322.439,86.734 h1.52
  text "SEMI-GLOSS" at 338.125,86.717 h1.52
  text "IMMERSION GOLD (ENIG)" at 314.819,82.345 h1.52
  text "ENEPIG" at 348.793,82.162 h1.52
  text "SURFACE FINISH:" at 287.87,82.136 h1.52
  text "X" at 310.298,82.136 h1.52
  text "IMM. TIN/SILVER OR EQUIV" at 296.24,78.649 h1.52
  text "OTHER" at 332.599,78.549 h1.52
  text "ARRAY/PANEL:" at 287.87,74.602 h1.52
  text "CUT AND TRIM PER M1 BOARD OUTLINE" at 314.819,74.393 h1.52
  text "N.C. ROUTE" at 314.819,70.94 h1.52
  text "X" at 332.295,70.94 h1.52
  text "V. SCORE" at 336.816,70.94 h1.52
  text "CERTIFICATION:" at 287.87,67.66 h1.52
  text "MATERIALS AND WORKMANSHIP FOR ALL PCBS" at 306.285,67.66 h1.52
  text "TO MEET OR EXCEED THE REQUIREMENTS OF:" at 306.285,65.271 h1.52
  text "X" at 297.078,62.003 h1.52
  text "ANSI IPC-A-600F CLASS ->" at 300.329,62.003 h1.52
  text "X" at 342.188,62.003 h1.52
  text "2" at 344.982,62.003 h1.52
  text "1" at 336.981,61.965 h1.52
  text "3" at 353.973,61.965 h1.52
  text "X" at 317.702,58.252 h1.52
  text "RoHS" at 320.953,58.252 h1.52
  text "OTHER" at 337.321,58.252 h1.52
  text "PER ORDER" at 347.407,58.252 h1.52
  text "ALL BOARDS MUST MEET OR EXCEED UL94-V0 REQUIREMENTS." at 288.569,54.345 h1.52
  text "PCB MUST BEAR THE UL94V-0 UL REGISTERED MATERIAL ID NUMBER" at 288.569,51.397 h1.52
  text "ADDITIONAL REQUIREMENTS:" at 287.87,47.094 h1.52
  text "MICROSECTION:" at 289.769,44.373 h1.52
  text "YES" at 312.775,44.373 h1.52
  text "REQUIRED" at 334.657,40.707 h1.52
  text "BARE BOARD ELEC. TEST:" at 289.769,40.634 h1.52
  text "NONE" at 322.935,40.634 h1.52
  text "X" at 331.66,40.634 h1.52
  text "PER ORDER" at 349.693,40.634 h1.52
  text "XX MIL VIAS REQUIRE NON-CONDUCTIVE FILL AND PLANARIZE" at 294.04,35.428 h1.5
  text "XX MIL VIAS REQUIRE CONDUCTIVE FILL AND PLANARIZE" at 294.243,32.787 h1.52
  text "OUTER XX MIL TRACES REQUIRE 50 OHM SINGLE-ENDED IMPEDANCE" at 294.218,28.637 h1.47
  text "LAYER 2 & 3 (INNER LAYERS) XX MIL WIDE, XX MIL SPACE / TRACES REQUIRE 100 OHM DIFFERENTIAL IMPEDANCE" at 294.015,22.65 h1.52
  text ".Layer_Name" at 14.656,-21.806 h1.52
M11 Gerber Information:
  lines w0.254: -7.417,-23.626 160.223,-23.626 ; -7.417,-18.462 160.274,-18.462 ; -7.417,-13.297 -7.417,-28.791 94.31,-28.791 160.274,-28.791 160.274,-13.297 -7.404,-13.297 -7.404,-28.791 32.614,-28.791 ; 55.194,-28.791 55.194,-13.297 ; 87.376,-18.462 87.376,-13.297 ; 108.712,-18.462 108.712,-13.297 ; 124.511,-28.956 124.511,-23.804
  text "ALL ARTWORK VIEWED FROM TOP SIDE" at -5.804,-16.654 h1.52
  text "BOARD #:" at 57.099,-16.654 h1.52
  text ".PRJ_Number" at 70.955,-16.654 h1.52
  text "REV:" at 92.405,-16.654 h1.52
  text ".PCB_Rev" at 99.809,-16.654 h1.52
  text "SVN REV:" at 113.69,-16.654 h1.52
  text ".VersionControl_RevNumber" at 126.543,-16.654 h1.52
  text "LAYER NAME =" at -5.804,-21.806 h1.52
  text "TID #:" at 57.099,-21.819 h1.52
  text ".TID" at 70.955,-21.819 h1.52
  text "PLOT NAME =" at -5.804,-27.034 h1.52
  text ".plot_File_Name" at 14.656,-27.034 h1.52
  text "GENERATED    :" at 57.15,-27.034 h1.52
  text ".Print_Date" at 79.235,-27.034 h1.52
  text ".Print_Time" at 97.752,-27.034 h1.52
  text "TEXAS INSTRUMENTS" at 129.87,-27.034 h1.52
M12 Stackup:
  drawing of 198 lines, arcs and shapes, not listed
  text "Layer" at 247.841,200.811 h0.5
  text "Name" at 251.598,200.811 h0.5
  text "Material" at 259.688,200.811 h0.5
  text "Thickness" at 267.194,200.811 h0.5
  text "Constant" at 272.95,200.811 h0.5
  text "Board Layer Stack" at 278.04,200.811 h0.5
  text "1" at 247.841,199.811 h0.5
  text "Top Overlay" at 251.598,199.811 h0.5
  text "2" at 247.841,198.811 h0.5
  text "Top Solder" at 251.598,198.811 h0.5
  text "Solder Resist" at 259.688,198.811 h0.5
  text "0.40mil" at 267.194,198.811 h0.5
  text "3.5" at 272.95,198.811 h0.5
  text "3" at 247.841,197.811 h0.5
  text "Top Layer" at 251.598,197.811 h0.5
  text "Copper" at 259.688,197.811 h0.5
  text "1.40mil" at 267.194,197.811 h0.5
  text "4" at 247.841,196.811 h0.5
  text "Dielectric1" at 251.598,196.811 h0.5
  text "FR-4" at 259.688,196.811 h0.5
  text "59.20mil" at 267.194,196.811 h0.5
  text "4.8" at 272.95,196.811 h0.5
  text "5" at 247.841,195.811 h0.5
  text "Bottom Layer" at 251.598,195.811 h0.5
  text "Copper" at 259.688,195.811 h0.5
  text "1.40mil" at 267.194,195.811 h0.5
  text "6" at 247.841,194.811 h0.5
  text "Bottom Solder" at 251.598,194.811 h0.5
  text "Solder Resist" at 259.688,194.811 h0.5
  text "0.40mil" at 267.194,194.811 h0.5
  text "3.5" at 272.95,194.811 h0.5
  text "7" at 247.841,193.811 h0.5
  text "Bottom Overlay" at 251.598,193.811 h0.5
  text ".Layer_Name" at 14.656,-21.806 h1.52
M13 Component Bodies Top:
  text ".Layer_Name" at 14.656,-21.806 h1.52
M14 Component Bodies Bottom:
  text ".Layer_Name" at 14.656,-21.806 h1.52
M15 Courtyards Top:
  text ".Layer_Name" at 14.656,-21.806 h1.52
M16 Courtyards Bottom:
  text ".Layer_Name" at 14.656,-21.806 h1.52
Drill Drawing:
  circle w0.254: c134.965,81.379 r0.23
  lines w0.254: 134.735,82.3 134.85,82.3 134.965,82.185 135.08,82.3 135.195,82.3 135.08,82.415 135.195,82.53 135.08,82.53 134.965,82.645 134.85,82.53 134.735,82.53 134.85,82.415 134.735,82.3 ; 134.735,83.22 134.735,83.335 134.85,83.45 134.735,83.565 134.735,83.681 134.85,83.681 134.965,83.565 135.08,83.681 135.195,83.681 135.195,83.565 135.08,83.45 135.195,83.335 135.195,83.22 135.08,83.22 134.965,83.335 134.85,83.22 134.735,83.22 ; 134.735,84.486 134.965,84.256 135.195,84.486 134.965,84.716 134.735,84.486 ; 134.735,85.291 135.195,85.291 135.195,85.752 134.735,85.752 134.735,85.291 ; 134.735,86.327 134.965,86.442 135.195,86.327 135.08,86.557 135.195,86.787 134.965,86.672 134.735,86.787 134.85,86.557 134.735,86.327
  lines w0.305: 134.264,80.839 161.15,80.839 ; 134.264,87.052 161.15,87.052 ; 137.075,79.803 137.075,88.087 ; 139.837,79.803 139.837,88.087 ; 145.13,79.803 145.13,88.087 ; 147.286,79.803 147.286,88.087 ; 150.406,79.803 150.406,88.087 ; 156.439,79.803 156.439,88.087 ; 134.264,79.803 161.15,79.803 161.15,88.087 134.264,88.087 134.264,79.803
  text "Symbol" at 134.886,87.362 h0.6
  text "Quantity" at 137.386,87.362 h0.6
  text "Finished Hole Size" at 140.147,87.362 h0.6
  text "Plated" at 145.441,87.362 h0.6
  text "Hole Type" at 147.596,87.362 h0.6
  text "Drill Layer Pair" at 150.717,87.362 h0.6
  text "Hole Tolerance" at 156.75,87.362 h0.6
  text "28" at 137.386,86.327 h0.5
  text "11.81mil (0.300mm)" at 140.147,86.327 h0.5
  text "PTH" at 145.441,86.327 h0.5
  text "Round" at 147.596,86.327 h0.5
  text "Top Layer - Bottom Layer" at 150.717,86.327 h0.5
  text "1" at 137.386,85.291 h0.5
  text "19.69mil (0.500mm)" at 140.147,85.291 h0.5
  text "PTH" at 145.441,85.291 h0.5
  text "Round" at 147.596,85.291 h0.5
  text "Top Layer - Bottom Layer" at 150.717,85.291 h0.5
  text "4" at 137.386,84.256 h0.5
  text "33.47mil (0.850mm)" at 140.147,84.256 h0.5
  text "PTH" at 145.441,84.256 h0.5
  text "Round" at 147.596,84.256 h0.5
  text "Top Layer - Bottom Layer" at 150.717,84.256 h0.5
  text "2" at 137.386,83.22 h0.5
  text "35.43mil (0.900mm)" at 140.147,83.22 h0.5
  text "PTH" at 145.441,83.22 h0.5
  text "Round" at 147.596,83.22 h0.5
  text "Top Layer - Bottom Layer" at 150.717,83.22 h0.5
  text "14" at 137.386,82.185 h0.5
  text "37.00mil (0.940mm)" at 140.147,82.185 h0.5
  text "PTH" at 145.441,82.185 h0.5
  text "Round" at 147.596,82.185 h0.5
  text "Top Layer - Bottom Layer" at 150.717,82.185 h0.5
  text "9" at 137.386,81.149 h0.5
  text "39.37mil (1.000mm)" at 140.147,81.149 h0.5
  text "PTH" at 145.441,81.149 h0.5
  text "Round" at 147.596,81.149 h0.5
  text "Top Layer - Bottom Layer" at 150.717,81.149 h0.5
  text "58 Total" at 137.386,80.114 h0.5
  text ".Layer_Name" at 14.656,-21.806 h1.52
M17 Embedded Cavity:
  text ".Layer_Name" at 14.656,-21.806 h1.52
M18 Embedded Assembly:
  text ".Layer_Name" at 14.656,-21.806 h1.52
M19 Embedded Keepout:
  text ".Layer_Name" at 14.656,-21.806 h1.52

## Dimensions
0,-10.16 to 25.4,-10.16 on M2 Board Dimensions
0,0 to 0,30 on M2 Board Dimensions
0,0 to 48,0.025 on M2 Board Dimensions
